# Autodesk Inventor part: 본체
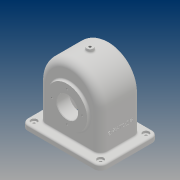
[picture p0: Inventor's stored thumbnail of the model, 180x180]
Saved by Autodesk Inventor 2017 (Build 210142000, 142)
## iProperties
Part Number: 본체
Material: 일반
Document SubType Name: Modeling
Designer: 20
Density: 1 g/cm^3
Appearance: 기본값
Mass: 404.407 g
Surface Area: 1182.65 cm^2
Volume: 404.407 cm^3
Author: 20
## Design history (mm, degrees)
sketch "스케치4"
  geometry: L1 (58, 13)-(58, -65); L2 (-58, 13)-(-58, -65); L3 (58, -65)-(-58, -65); A1 r 58 centre (0, 13) between (58, 13) and (-58, 13); 1 further point
  constraints: 6 end point, 2 point on circle, 2 tangent, 2 vertical, 1 centre point, 1 horizontal, 1 vertical alignment
  dimensions: "d10" = 116 diameter of A1; "d11" = 13 distance of point (0, 0) A1.centre; "d12" = 78 distance from line of L3 A1.centre
extrude "돌출2" new body sketch "스케치4" stored distance "d13" = 77; taper "d14" = 0 deg
sketch "스케치7"
  geometry: C1 r 38 at (0, 0); 1 further point
  constraints: 1 centre point, 1 coincident
  dimensions: "d22" = 76 diameter of C1
extrude "돌출3" join sketch "스케치7" distance "d23" = 5; taper "d24" = 0 deg
sketch "스케치8"
  geometry: C1 r 38 at (0, 0); 1 further point
  constraints: 1 centre point, 1 coincident
  dimensions: "d25" = 76 diameter of C1
extrude "돌출4" join sketch "스케치8" distance "d26" = 10; taper "d27" = 0 deg
sketch "스케치10"
  geometry: L1 (133, -93.5)-(-17, -93.5); L2 (-17, -93.5)-(-17, 16.5); L3 (-17, 16.5)-(133, 16.5); L4 (133, 16.5)-(133, -93.5); L5 (133, -93.5)-(-17, 16.5); L6 (-17, -93.5)-(133, 16.5); 1 further point
  constraints: 12 end point, 2 midpoint, 2 parallel, 1 horizontal, 1 perpendicular
  dimensions: "d29" = 150 distance of L2.end L3.end; "d30" = 110 distance of L1.end L2.end
extrude "돌출5" join sketch "스케치10" distance "d31" = 10; taper "d32" = 0 deg
sketch "스케치12"
  geometry: L1 (52, 13)-(52, -65); L2 (-52, 13)-(-52, -65); L3 (52, -65)-(-52, -65); L4 (-75, -65)-(75, -65) reference; A1 r 52 centre (0, 13) between (52, 13) and (-52, 13); A2 r 58 centre (0, 13) between (58, 13) and (-58, 13) reference; 1 further point
  constraints: 6 end point, 2 point on circle, 2 tangent, 2 vertical, 1 centre point, 1 collinear, 1 concentric, 1 horizontal
  dimensions: "d33" = 104 diameter of A1
extrude "돌출6" cut sketch "스케치12" stored distance "d34" = 67; taper "d35" = 0 deg
sketch "스케치13"
  geometry: C1 r 28 at (0, 0); 1 further point
  constraints: 1 centre point, 1 coincident
  dimensions: "d36" = 56 diameter of C1
extrude "돌출7" join sketch "스케치13" distance "d37" = 14; taper "d38" = 0 deg
feature "면 기울기1" dims angle "d39" = 40 deg
sketch "스케치14"
  geometry: C1 r 20 at (0, 0); 1 further point
  constraints: 1 centre point, 1 coincident
  dimensions: "d40" = 40 diameter of C1
extrude "돌출8" cut sketch "스케치14" stored distance "d41" = 14; taper "d42" = 0 deg
node "작업 평면2"
sketch "스케치16"
  geometry: L1 (150, 110)-(150, 0) reference; L2 (150, 0)-(0, 0) reference; C1 r 6 at (75, 55); 1 further point
  constraints: 1 centre point
  dimensions: "d44" = 12 diameter of C1; "d45" = 75 distance from line of L1 C1.centre; "d46" = 55 distance from line of L2 C1.centre
extrude "돌출9" join sketch "스케치16" stored distance "d47" = 14; taper "d48" = 0 deg
sketch "스케치17"
  geometry: 2 further points
  constraints: 1 vertical alignment
  dimensions: "d49" = 29 distance of point (0, 0) point (0, 29)
hole "구멍1" sketch "스케치17" at (0, 29) diameter "d50" = 3.242; stored, may be unused: countersink angle "d54" = 90 deg, drill point angle "d56" = 118 deg; dims "d51" = 8, "d52" = 4, "d53" = 2, "d55" = 10
sketch "스케치18"
  geometry: 2 further points
  constraints: 1 vertical alignment
  dimensions: "d60" = 29 distance of point (0, 0) point (0, -29)
hole "구멍2" sketch "스케치18" at (0, -29) diameter "d61" = 3.242; stored, may be unused: countersink angle "d65" = 90 deg, drill point angle "d67" = 118 deg; dims "d62" = 8, "d63" = 4, "d64" = 2, "d66" = 10
fillet "모깎기1" dims "d71" = 12
fillet "모깎기2" dims "d72" = 3
sketch "스케치19"
  geometry: L1 (-133, 4.5)-(-133, -81.5) reference; L2 (-121, -93.5)-(5, -93.5) reference; 2 further points
  dimensions: "d73" = 12 distance from line of L1 point (-121, -81.5); "d74" = 12 distance from line of L2 point (-121, -81.5)
hole "구멍3" sketch "스케치19" at (-121, -81.5) diameter "d75" = 5; stored, may be unused: countersink angle "d79" = 90 deg, drill point angle "d81" = 118 deg; dims "d76" = 8, "d77" = 12, "d78" = 4, "d80" = 10
fillet "모깎기3" dims "d88" = 13
hole "구멍4" diameter "d92" = 4.459; stored, may be unused: countersink angle "d96" = 90 deg, drill point angle "d98" = 118 deg; dims "d90" = 10, "d91" = 10, "d93" = 10, "d94" = 12, "d95" = 4, "d97" = 12.8
fillet "모깎기5" dims "d99" = 8
fillet "모깎기6" dims "d100" = 3
fillet "모깎기7" dims "d101" = 3
node "작업 평면3"
sketch "스케치20"
  geometry: L1 (78, -17.5)-(78, 68.5) reference; L2 (0, -13)-(65, -13) reference; 2 further points
  constraints: 1 other
  dimensions: "d103" = 40 distance from line of L1 point (38, 25.5); "d104" = 38.5 distance from line of L2 point (38, 25.5)
feature "엠보싱1" sketch "스케치20" dims "d10" = 116, "d11" = 13, "d12" = 78, "d29" = 150, "d30" = 110, "d105" = 0.5, "d106" = 0
feature "면 기울기2" dims angle "d107" = 5 deg
fillet "모깎기8" dims "d108" = 3
chamfer "모따기1" distance "d109" = 1; stored, may be unused: second distance "d110" = 2, angle "d111" = 45 deg
node "솔리드2"
pattern_circular "원형 패턴1" dims angle "d58" = 360 deg
pattern_circular "원형 패턴2" dims angle "d69" = 360 deg
pattern_linear "직사각형 패턴1" dims "d84" = 86, "d87" = 126
other parameters: "d43" = -142
